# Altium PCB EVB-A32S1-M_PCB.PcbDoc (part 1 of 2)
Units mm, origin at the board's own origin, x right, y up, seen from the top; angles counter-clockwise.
Board outline 134 x 65 mm, 4 copper layers (L1 (Signal), L2 (GND), L3 (PWR), L4 (Signal)), stack 1.553 mm thick; 111 components, 86 nets, 414 pads, 386 vias.
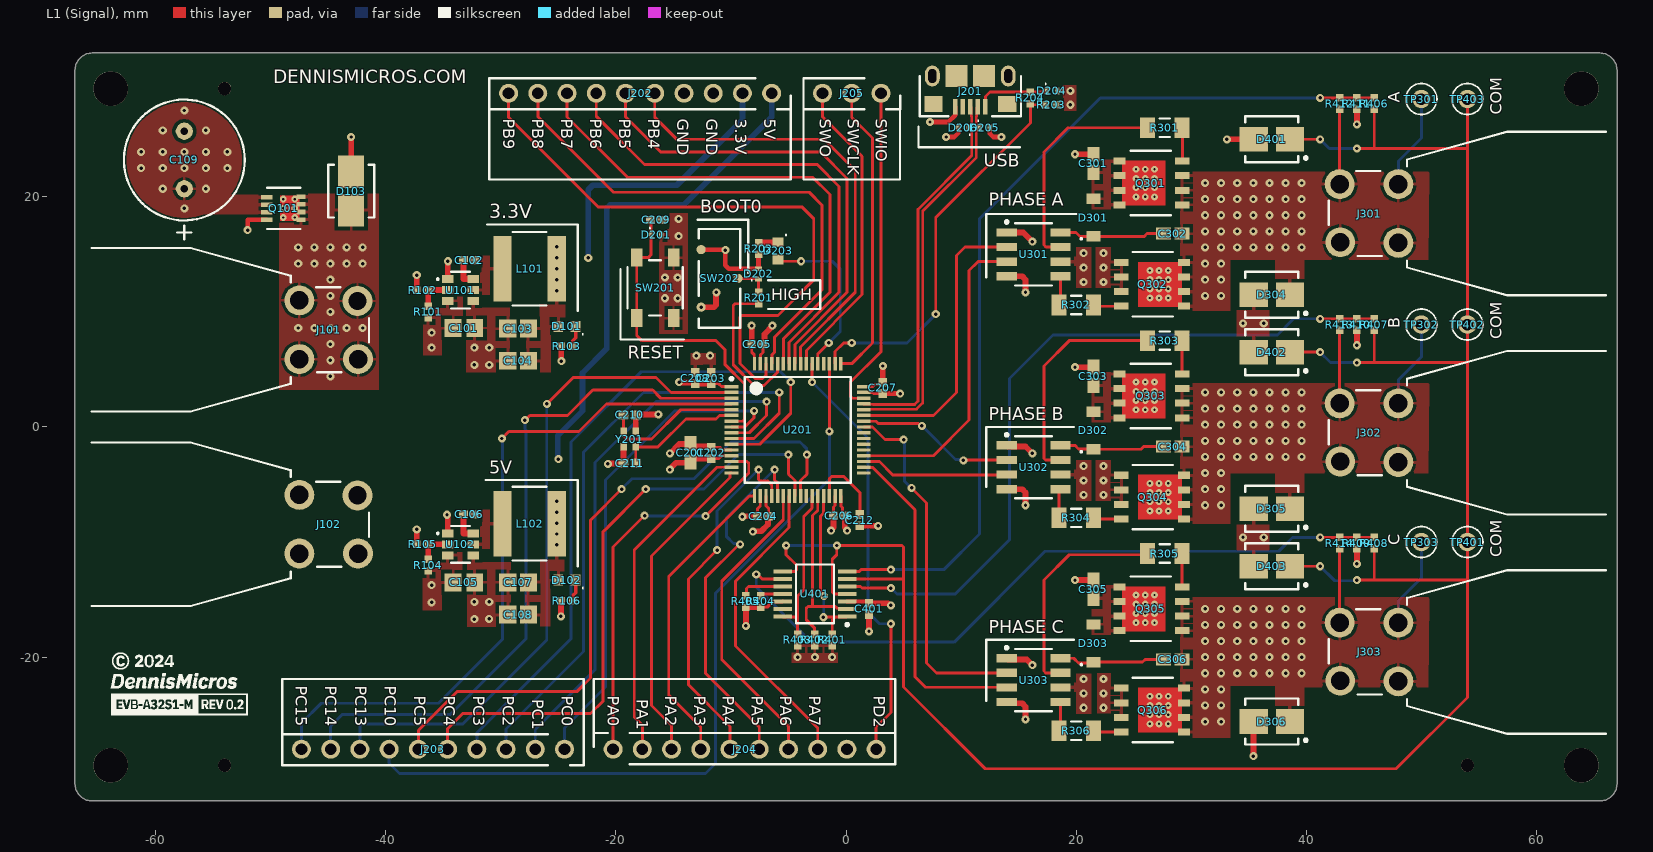
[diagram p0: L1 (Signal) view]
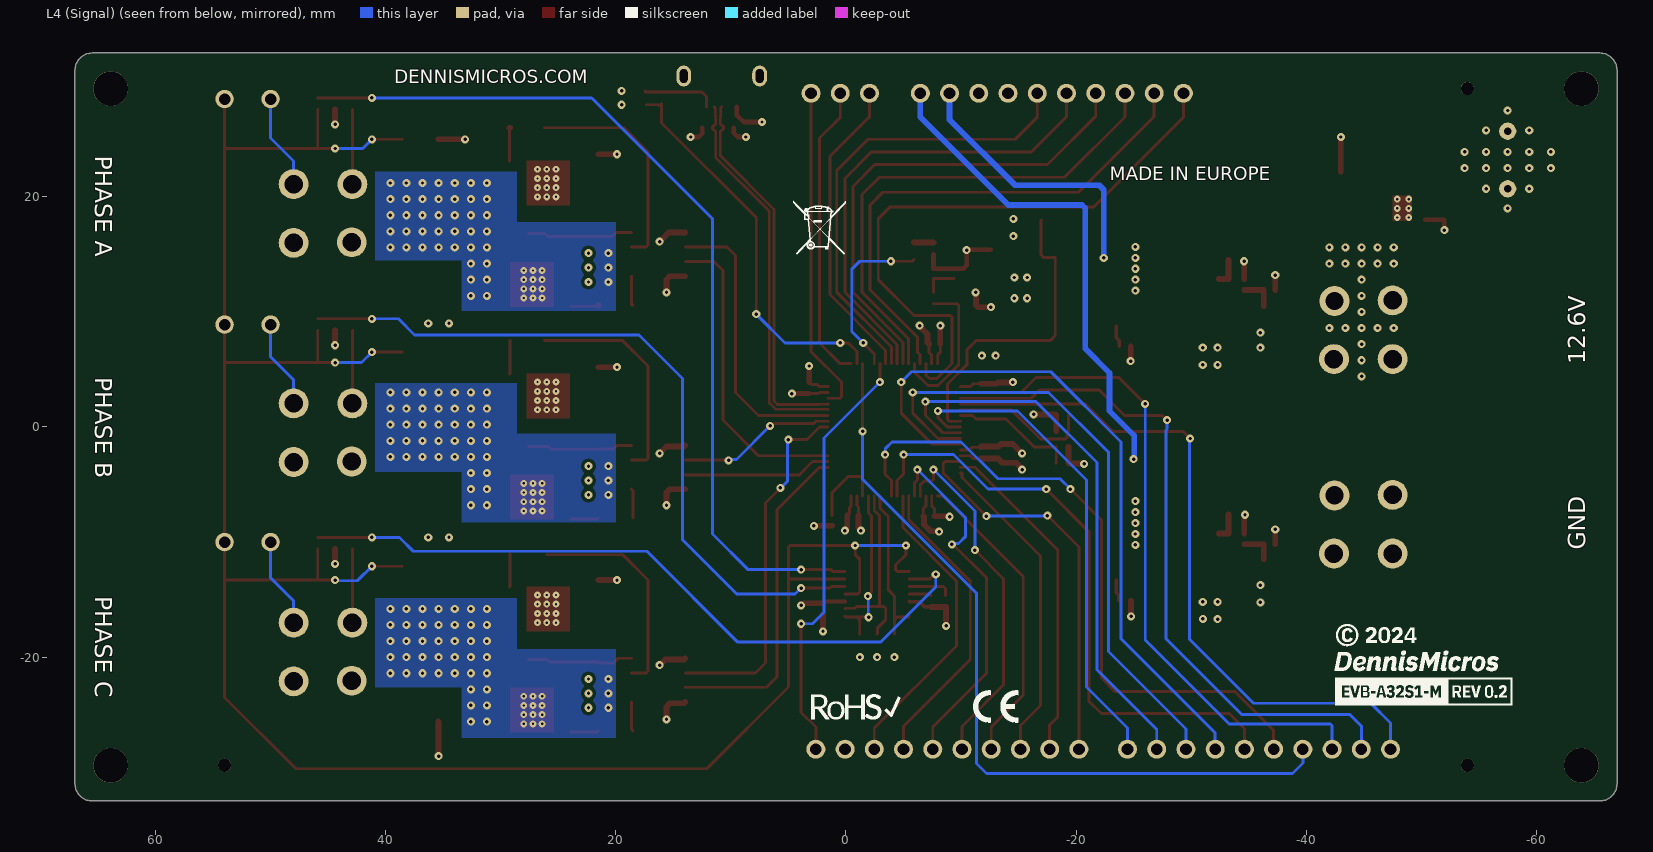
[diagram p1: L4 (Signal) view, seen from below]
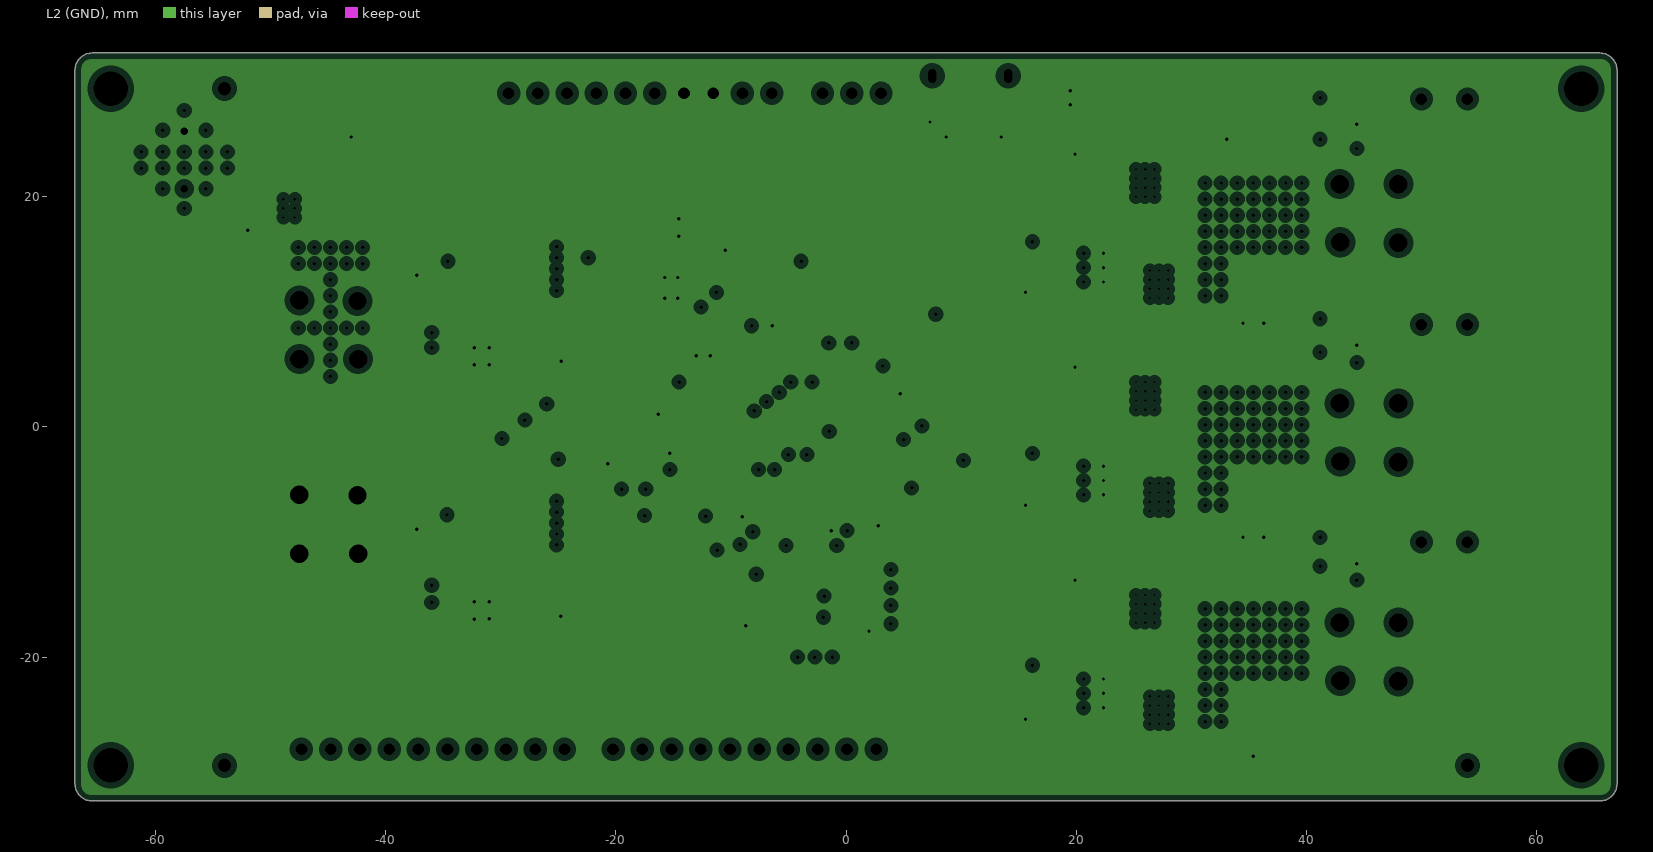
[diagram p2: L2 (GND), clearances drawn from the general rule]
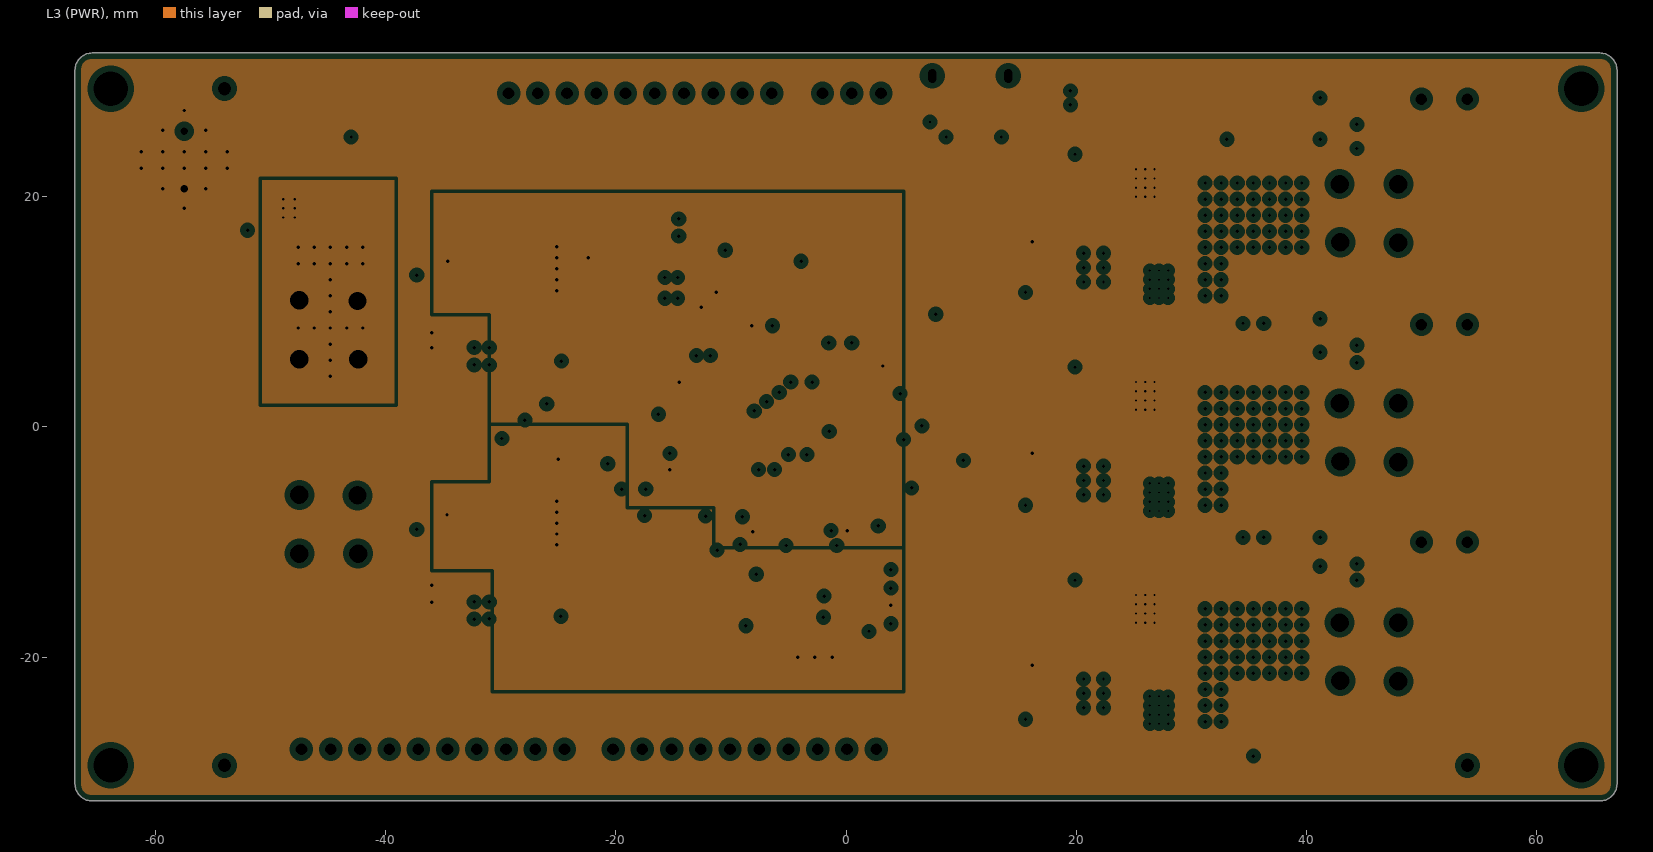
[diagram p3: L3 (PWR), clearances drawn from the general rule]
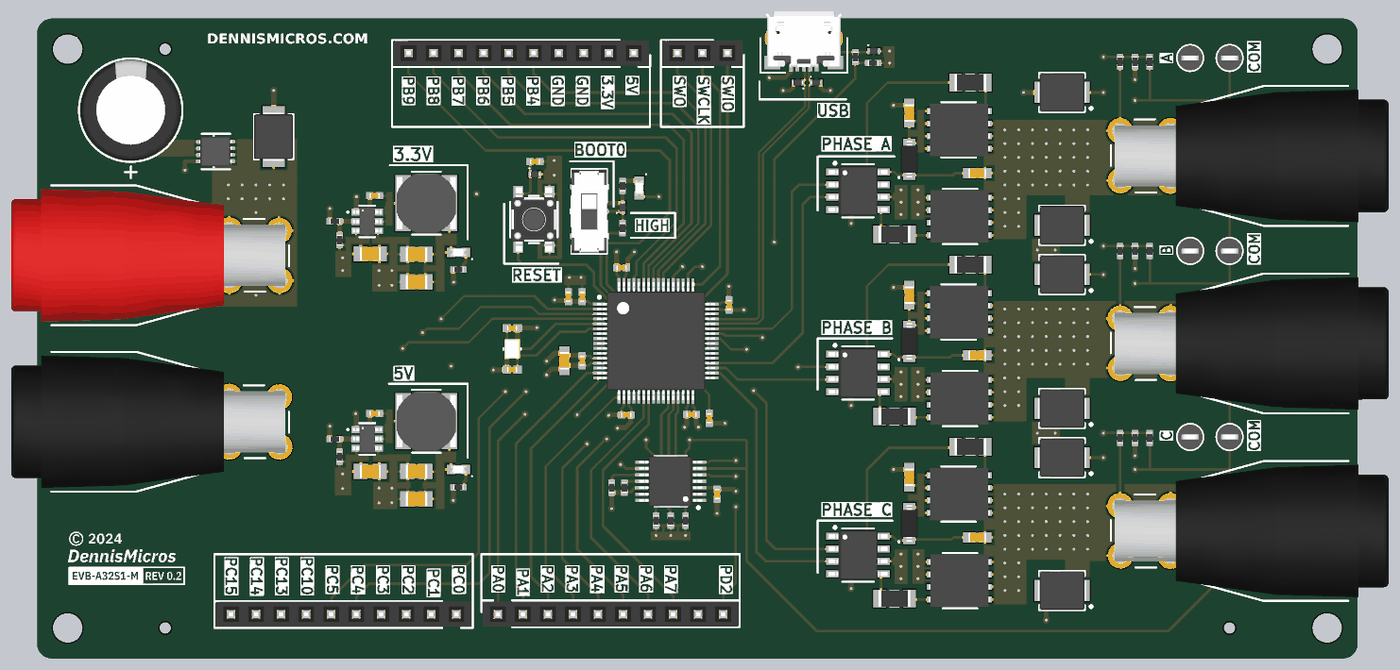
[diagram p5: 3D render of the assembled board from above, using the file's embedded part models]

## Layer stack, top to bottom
Top Solder: solder mask 0.025, SM-Peters-AS-2467-SM-DG, Dk 3.7
L1 (Signal): signal copper 0.04
PP1_1080: prepreg 0.0681, Panasonic 1080 / R-1551 (W), Dk 4.3
PP2_1080: prepreg 0.0681, Panasonic 1080 / R-1551 (W), Dk 4.3
L2 (GND): plane copper 0.035, net GND
C_FR4: core 1.13, Panasonic FR4 / R-1566(W), Dk 4.6
L3 (PWR): plane copper 0.035, net (Multiple Nets)
PP3_1080: prepreg 0.0681, Panasonic 1080 / R-1551 (W), Dk 4.3
PP4_1080: prepreg 0.0681, Panasonic 1080 / R-1551 (W), Dk 4.3
L4 (Signal): signal copper 0.04
Bottom Solder: solder mask 0.025, SM-Peters-AS-2467-SM-DG, Dk 3.7

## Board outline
-67,-31 -67,31 cw(c-65.5,31) -65.5,32.5 65.5,32.5 cw(c65.5,31) 67,31 67,-31 cw(c65.5,-31) 65.5,-32.5 -65.5,-32.5 cw(c-65.5,-31)

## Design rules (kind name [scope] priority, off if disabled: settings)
BoardOutlineClearance CopperBoardOutlineClearance [IsText = 'False'] p1: gap=0.305 ignorepadtopadclearanceinfootprint=FALSE
BoardOutlineClearance SilkscreenBoardOutlineClearance [IsText = 'True'] p2: gap=0.4 ignorepadtopadclearanceinfootprint=FALSE
Clearance [All] p1: gap=0.3 ignorepadtopadclearanceinfootprint=FALSE except(0.125: Arc-Arc Arc-Track Arc-SMDPad Arc-Text Track-Track Track-SMDPad Track-Text SMDPad-SMDPad SMDPad-Fill SMDPad-Poly SMDPad-Region SMDPad-Text THPad-Text Via-Text Fill-Fill Fill-Poly Fill-Region Fill-Text Poly-Poly Poly-Region Poly-Text Region-Region Region-Text Text-Text Text-Hole)
DiffPairsRouting DiffUSBRouting [InDifferentialPairClass('DIFF_USB')] p1: maxlimit=0.165 minlimit=0.165 mostfreqgap=0.165 toplayer_minwidth=0.23 toplayer_maxwidth=0.23 toplayer_prefwidth=0.23 bottomlayer_minwidth=0.23 bottomlayer_maxwidth=0.23 bottomlayer_prefwidth=0.23 impedanceprofiledriven=TRUE impedanceprofileid={3CFC2630-1907-411B-A5D9-8473F3C0A9A4} impedanceprofilevalue=90.000000 maxuncoupledlength=12.7
HoleSize NPTHSlotSize [HoleType = 'Slot' && PadIsPlated = 'False'] p1: absolutevalues=TRUE maxlimit=5.6 minlimit=1.8 maxpercent=80.000 minpercent=20.000
HoleSize PTHSlotSize [HoleType = 'Slot' && PadIsPlated = 'True'] p2: absolutevalues=TRUE maxlimit=2.6 minlimit=0.7 maxpercent=80.000 minpercent=20.000
HoleSize PTHSize [PadIsPlated = 'True'] p3: absolutevalues=TRUE maxlimit=5.6 minlimit=0.5 maxpercent=80.000 minpercent=20.000
HoleSize NPTHSize [PadIsPlated = 'False'] p4: absolutevalues=TRUE maxlimit=5.6 minlimit=0.5 maxpercent=80.000 minpercent=20.000
HoleToHoleClearance [All] p1: gap=0.3 allowstackedmicrovias=TRUE
MinimumAnnularRing PTHSlotMinimumAnnularRing [HoleType = 'Slot' && PadIsPlated = 'True'] p1: minimumring=0.3
MinimumAnnularRing PTHMinimumAnnularRing [PadIsPlated = 'True'] p2: minimumring=0.3
MinimumAnnularRing ViaMinimumAnnularRing [IsVia] p3: minimumring=0.1
MinimumSolderMaskSliver [All] p1: minsoldermaskwidth=0.075
PlaneClearance [All] p1: clearance=0.508
PlaneConnect [All] p1: pad.planeconnectstyle=Relief pad.reliefexpansion=0.508 pad.reliefentries=4 pad.reliefconductorwidth=0.254 pad.reliefairgap=0.3 via.planeconnectstyle=Direct via.reliefexpansion=0.508 via.reliefentries=4 via.reliefconductorwidth=0.254 via.reliefairgap=0.254
PolygonConnect [All] p1: thpad.connectstyle=Relief thpad.reliefconductorwidth=0.254 thpad.reliefentries=4 thpad.polygonreliefangle="90 Angle" thpad.airgapwidth=0.3 smdpad.connectstyle=Relief smdpad.reliefconductorwidth=0.254 smdpad.reliefentries=4 smdpad.polygonreliefangle="90 Angle" smdpad.airgapwidth=0.3 via.connectstyle=Direct via.reliefconductorwidth=0.254 via.reliefentries=4 via.polygonreliefangle="90 Angle" via.airgapwidth=0.254
RoutingVias [All] p1: holewidth=0.3 width=0.7 viastyle="Through Hole" minholewidth=0.25 minwidth=0.5 maxholewidth=0.45 maxwidth=0.7
SilkToSilkClearance [All] p1: silktosilkclearance=0.3
SilkToSolderMaskClearance [IsPad] p1: minsilkscreentomaskgap=0.15 clearancetoexposedcopper=TRUE
SolderMaskExpansion [All] p1: expansion=0.127 istentingtop=FALSE
SupplyNets "Schematic Supply Nets_2" [InNet('+VBAT')] p1: voltage=0.000
SupplyNets "Schematic Supply Nets_4" [InNet('GND')] p2: voltage=0.000
SupplyNets "Schematic Supply Nets_3" [InNet('+VCC')] p3: voltage=0.000
SupplyNets "Schematic Supply Nets_1" [InNet('+5V')] p4: voltage=0.000
SupplyNets "Schematic Supply Nets" [InNet('+3V3')] p5: voltage=0.000
UnRoutedNet [All] p1: checkbadconnections=TRUE
Width [All] p1: maxlimit=1 minlimit=0.15 preferedwidth=0.25
21 further rules are at their usual default settings.

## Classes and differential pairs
differential pair class DIFF_USB: USB_D
component class 4_EVB-A32S1-M_Sensing: C401 D401 D402 D403 R401 R402 R403 R404 R405 R406 R407 R408 R409 R410 R411 R412 R413 R414 TP401 TP402 TP403 U401
component class 3_EVB-A32S1-M_Motor: C301 C302 C303 C304 C305 C306 D301 D302 D303 D304 D305 D306 J301 J302 J303 Q301 Q302 Q303 Q304 Q305 Q306 R301 R302 R303 R304 R305 R306 TP301 TP302 TP303 U301 U302 U303
component class 2_EVB-A32S1-M_MCU: C201 C202 C203 C204 C205 C206 C207 C208 C209 C210 C211 C212 D201 D202 D203 D204 D205 D206 J201 J202 J203 J204 J205 R201 R202 R203 R204 SW201 SW202 U201 Y201
component class 1_EVB-A32S1-M_Power: C101 C102 C103 C104 C105 C106 C107 C108 C109 D101 D102 D103 J101 J102 L101 L102 Q101 R101 R102 R103 R104 R105 R106 U101 U102
differential pair USB_D: +USB_D_P -USB_D_N

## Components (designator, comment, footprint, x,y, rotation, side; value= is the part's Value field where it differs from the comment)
C101 "CL21A106KOQNNNE" C_Samsung_CL_0805_A -33.2,8.6 r180 top value=10uF
C102 "CL05B104KP5NNNC" C_Samsung_CL_0402_A -32.75,14.5 r180 top value=100nF
C103 "CC0805MKX5R6BB226" C_Yageo_CC_0805_A -28.5,8.55 r0 top value=22uF
C104 "CC0805MKX5R6BB226" C_Yageo_CC_0805_A -28.5,5.75 r0 top value=22uF
C105 "CL21A106KOQNNNE" C_Samsung_CL_0805_A -33.2,-13.5 r180 top value=10uF
C106 "CL05B104KP5NNNC" C_Samsung_CL_0402_A -32.75,-7.6 r180 top value=100nF
C107 "CC0805MKX5R6BB226" C_Yageo_CC_0805_A -28.5,-13.5 r0 top value=22uF
C108 "CC0805MKX5R6BB226" C_Yageo_CC_0805_A -28.5,-16.3 r0 top value=22uF
C109 "35ZLH470MEFC10X16" C_Rubycon_10x16mm_TH -57.5,23.2 r90 top value=470uF
C201 "CC0603KRX7R7BB105" C_Yageo_CC_0603_A -13.5,-2.25 r270 top value=1uF
C202 "CL05B104KP5NNNC" C_Samsung_CL_0402_A -11.7,-2.25 r270 top value=100nF
C203 "CL05B104KP5NNNC" C_Samsung_CL_0402_A -11.7,4.25 r270 top value=100nF
C204 "CL05B104KP5NNNC" C_Samsung_CL_0402_A -7.2,-7.75 r0 top value=100nF
C205 "CL05B104KP5NNNC" C_Samsung_CL_0402_A -7.7,7.2 r180 top value=100nF
C206 "CL05B104KP5NNNC" C_Samsung_CL_0402_A -0.6,-7.7 r0 top value=100nF
C207 "CL05B104KP5NNNC" C_Samsung_CL_0402_A 3.2,3.4 r90 top value=100nF
C208 "CL05A475MP5NRNC" C_Samsung_CL_0402_A -13.1,4.25 r270 top value=4.7uF
C209 "CL05B104KP5NNNC" C_Samsung_CL_0402_A -16.488,17.988 r180 top value=100nF
C210 "CC0402JRNPO9BN150" C_Yageo_CC_0402_A -18.8,1.05 r180 top value=15pF
C211 "CC0402JRNPO9BN150" C_Yageo_CC_0402_A -18.8,-3.15 r0 top value=15pF
C212 "CL05A475MP5NRNC" C_Samsung_CL_0402_A 1.2,-8.1 r90 top value=4.7uF
C301 "CC0603KRX7R7BB105" C_Yageo_CC_0603_A 21.5,22.9 r270 top value=1uF
C302 "CC0603KRX7R7BB105" C_Yageo_CC_0603_A 28.4,16.8 r180 top value=1uF
C303 "CC0603KRX7R7BB105" C_Yageo_CC_0603_A 21.5,4.4 r270 top value=1uF
C304 "CC0603KRX7R7BB105" C_Yageo_CC_0603_A 28.4,-1.7 r180 top value=1uF
C305 "CC0603KRX7R7BB105" C_Yageo_CC_0603_A 21.5,-14.1 r270 top value=1uF
C306 "CC0603KRX7R7BB105" C_Yageo_CC_0603_A 28.4,-20.2 r180 top value=1uF
C401 "CL05B104KP5NNNC" C_Samsung_CL_0402_A 2,-15.8 r90 top value=100nF
D101 "LTST-C190GKT" D_LED_Lite-On_Green_0603_A -24.25,8.75 r180 top
D102 "LTST-C190GKT" D_LED_Lite-On_Green_0603_A -24.25,-13.3 r180 top
D103 "SMBJ15CA-13-F" D_TVS_BI_Diodes_SMBJ15CA-13-F_A -43,20.5 r90 top value=280pF
D201 "D5V0F1U2S9-7" D_TVS_Uni_Diodes_SOD-923_B -16.488,16.688 r0 top value=5E-13F
D202 "D5V0F1U2S9-7" D_TVS_Uni_Diodes_SOD-923_B -7.588,13.312 r90 top value=5E-13F
D203 "LTST-C190GKT" D_LED_Lite-On_Green_0603_A -5.9,15.3 r270 top
D204 "D5V0F1U2S9-7" D_TVS_Uni_Diodes_SOD-923_B 17.9,29.2 r0 top value=5E-13F
D205 "D5V0F1U2S9-7" D_TVS_Uni_Diodes_SOD-923_B 12.05,26 r0 top value=5E-13F
D206 "D5V0F1U2S9-7" D_TVS_Uni_Diodes_SOD-923_B 10.2,26 r180 top value=5E-13F
D301 "B5819W-TP" D_Schottky_MCC_SOD-123 21.5,18.2 r90 top
D302 "B5819W-TP" D_Schottky_MCC_SOD-123 21.5,-0.3 r90 top
D303 "B5819W-TP" D_Schottky_MCC_SOD-123 21.5,-18.8 r90 top
D304 "SMBJ15A-13-F" D_TVS_Uni_Diodes_DO-214AA_B 37,11.5 r180 top value=800pF
D305 "SMBJ15A-13-F" D_TVS_Uni_Diodes_DO-214AA_B 37,-7.1 r180 top value=800pF
D306 "SMBJ15A-13-F" D_TVS_Uni_Diodes_DO-214AA_B 37,-25.6 r180 top value=800pF
D401 "SMBJ15A-13-F" D_TVS_Uni_Diodes_DO-214AA_B 37,25 r180 top value=800pF
D402 "SMBJ15A-13-F" D_TVS_Uni_Diodes_DO-214AA_B 37,6.5 r180 top value=800pF
D403 "SMBJ15A-13-F" D_TVS_Uni_Diodes_DO-214AA_B 37,-12.1 r180 top value=800pF
J101 "CT3151SP-2" J_CalTest_CT3151SP-2 -44.95,8.45 r0 top
J102 "CT3151SP-0" J_CalTest_CT3151SP-0 -44.95,-8.45 r0 top
J201 "10118193-0001LF" J_USB_Micro-B_Amphenol_10118193-0001LF 10.8,30.5 r180 top
J202 "PPPC101LFBN-RC" J_Sullins_01x07_Socket_2.54mm -17.89,29 r180 top
J203 "PPPC101LFBN-RC" J_Sullins_01x07_Socket_2.54mm -35.89,-28 r180 top
J204 "PPPC101LFBN-RC" J_Sullins_01x07_Socket_2.54mm -8.81,-28 r0 top
J205 "PPPC031LFBN-RC" J_Sullins_01x03_Socket_2.54mm 0.5,29 r180 top
J301 "CT3151SP-0" J_CalTest_CT3151SP-0 45.45,18.55 r180 top
J302 "CT3151SP-0" J_CalTest_CT3151SP-0 45.45,-0.5 r180 top
J303 "CT3151SP-0" J_CalTest_CT3151SP-0 45.45,-19.55 r180 top
L101 "1255AY-3R9N=P3" L_Murata_1255AY-XXXX=P3 -27.5,13.75 r0 top value=3.9uH
L102 "1255AY-4R7M=P3" L_Murata_1255AY-XXXX=P3 -27.5,-8.4 r0 top value=4.7uH
Q101 "SI7617DN-T1-GE3" Q_Vishay_PowerPACK-1212-8 -48.9,19 r0 top
Q301 "SIR182DP-T1-RE3" Q_Vishay_PowerPACK-SO-8-Single 26.75,21.2 r180 top
Q302 "SIR182DP-T1-RE3" Q_Vishay_PowerPACK-SO-8-Single 26.4,12.4 r0 top
Q303 "SIR182DP-T1-RE3" Q_Vishay_PowerPACK-SO-8-Single 26.75,2.7 r180 top
Q304 "SIR182DP-T1-RE3" Q_Vishay_PowerPACK-SO-8-Single 26.4,-6.1 r0 top
Q305 "SIR182DP-T1-RE3" Q_Vishay_PowerPACK-SO-8-Single 26.75,-15.8 r180 top
Q306 "SIR182DP-T1-RE3" Q_Vishay_PowerPACK-SO-8-Single 26.4,-24.6 r0 top
R101 "RC0402FR-07110KL" R_Yageo_RCL_0402_A -36.3,10 r270 top value=110kR
R102 "RC0402FR-0713KL" R_Yageo_RCL_0402_A -36.8,11.9 r0 top value=13kR
R103 "RC0402FR-071KL" R_Yageo_RCL_0402_A -24.25,7 r0 top value=1kR
R104 "RC0402FR-07110KL" R_Yageo_RCL_0402_A -36.3,-12 r270 top value=110kR
R105 "RC0402FR-0713KL" R_Yageo_RCL_0402_A -36.8,-10.2 r0 top value=13kR
R106 "RC0402FR-071KL" R_Yageo_RCL_0402_A -24.25,-15.1 r0 top value=1kR
R201 "RC0402FR-0710KL" R_Yageo_RCL_0402_A -7.588,11.212 r270 top value=10kR
R202 "RC0402FR-071KL" R_Yageo_RCL_0402_A -7.6,15.5 r90 top value=1kR
R203 "RC0402FR-0733KL" R_Yageo_RCL_0402_A 17.825,28 r180 top value=33kR
R204 "RC0402FR-0713KL" R_Yageo_RCL_0402_A 16.025,28.6 r90 top value=13kR
R301 "RC1206FR-07100RL" R_Yageo_RCL_1206_A 27.7,26 r0 top value=100R
R302 "RC1206FR-07100RL" R_Yageo_RCL_1206_A 20,10.6 r0 top value=100R
R303 "RC1206FR-07100RL" R_Yageo_RCL_1206_A 27.7,7.5 r0 top value=100R
R304 "RC1206FR-07100RL" R_Yageo_RCL_1206_A 20,-7.9 r0 top value=100R
R305 "RC1206FR-07100RL" R_Yageo_RCL_1206_A 27.7,-11 r0 top value=100R
R306 "RC1206FR-07100RL" R_Yageo_RCL_1206_A 20,-26.4 r0 top value=100R
R401 "RC0402FR-0710KL" R_Yageo_RCL_0402_A -1.2,-18.5 r270 top value=10kR
R402 "RC0402FR-0710KL" R_Yageo_RCL_0402_A -2.7,-18.5 r270 top value=10kR
R403 "RC0402FR-0710KL" R_Yageo_RCL_0402_A -4.2,-18.5 r270 top value=10kR
R404 "RC0402FR-0710KL" R_Yageo_RCL_0402_A -7.4,-15.15 r90 top value=10kR
R405 "RC0402FR-0710KL" R_Yageo_RCL_0402_A -8.7,-15.15 r90 top value=10kR
R406 "RC0402FR-0733KL" R_Yageo_RCL_0402_A 45.9,28.1 r90 top value=33kR
R407 "RC0402FR-0733KL" R_Yageo_RCL_0402_A 45.9,8.9 r90 top value=33kR
R408 "RC0402FR-0733KL" R_Yageo_RCL_0402_A 45.9,-10.1 r90 top value=33kR
R409 "RC0402FR-0710KL" R_Yageo_RCL_0402_A 44.4,-10.1 r90 top value=10kR
R410 "RC0402FR-0710KL" R_Yageo_RCL_0402_A 44.4,8.9 r90 top value=10kR
R411 "RC0402FR-0710KL" R_Yageo_RCL_0402_A 44.4,28.1 r90 top value=10kR
R412 "RC0402FR-0733KL" R_Yageo_RCL_0402_A 42.9,28.1 r270 top value=33kR
R413 "RC0402FR-0733KL" R_Yageo_RCL_0402_A 42.9,8.9 r270 top value=33kR
R414 "RC0402FR-0733KL" R_Yageo_RCL_0402_A 42.9,-10.1 r270 top value=33kR
SW201 "PTS647SN50SMTR2LFS" SW_Tactitle_SPST_C&K_PTS647SN50SMTR2LFS -16.588,12.088 r90 top
SW202 "JS102011JCQN" SW_Slide_C&K_JS102011JCQN -10.988,12.912 r270 top
TP301 "5001" TP_Keystone_TH 50,28.5 r90 top
TP302 "5001" TP_Keystone_TH 50,8.9 r90 top
TP303 "5001" TP_Keystone_TH 50,-10 r90 top
TP401 "5001" TP_Keystone_TH 54,-10 r90 top
TP402 "5001" TP_Keystone_TH 54,8.9 r90 top
TP403 "5001" TP_Keystone_TH 54,28.5 r90 top
U101 "AP63203WU-7" U_Diodes_AP623xx -33.5,11.9 r270 top
U102 "AP63205WU-7" U_Diodes_AP623xx -33.5,-10.2 r270 top
U201 "STM32F401RET6" U_ST_STM32F401xD/xE_B -4.2,-0.25 r0 top
U301 "IR2103STRPBF" U_Infineon_8-SOIC_3.9mm 16.3,15 r0 top
U302 "IR2103STRPBF" U_Infineon_8-SOIC_3.9mm 16.3,-3.5 r0 top
U303 "IR2103STRPBF" U_Infineon_8-SOIC_3.9mm 16.3,-22 r0 top
U401 "LM339APWR" U_TI_14-TSSOP-5.00x4.40mm_0.62mm_B -2.7,-14.5 r180 top
Y201 "ECS-240-12-37B-CKY-TR" Y_Crystal_GND24_ECS_240-12-37B-CKY-TR -18.8,-1.05 r270 top

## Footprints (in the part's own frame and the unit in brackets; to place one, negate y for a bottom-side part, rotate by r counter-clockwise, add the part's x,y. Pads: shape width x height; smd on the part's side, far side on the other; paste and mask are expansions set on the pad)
C_Rubycon_10x16mm_TH [mm]
  round 1.5 hole 0.65: 1(-2.5,0) 2(2.5,0)
  silkscreen extent -6.9,-5.25 5.25,5.25, body extent -5.11,-5.1 5.11,5.1, height 16.46
C_Samsung_CL_0402_A [mm] "Chip Capacitor, 2-Leads, Body 1.00x0.50mm, IPC Low Density"
  rect 0.76x0.72 smd mask+0.05: 1(-0.49,0) 2(0.49,0)
  body extent -0.53,-0.28 0.53,0.28, height 0.55
C_Samsung_CL_0805_A [mm] "Chip Capacitor, 2-Leads, Body 2.00x1.25mm, IPC Low Density"
  rect 1.45x1.55 smd: 1(-0.95,0) 2(0.95,0)
  body extent -1.07,-0.7 1.07,0.7, height 1.4
C_Yageo_CC_0402_A [mm] "Yageo series CC Chip Capacitor, 2-Leads, Body 1.00x0.50mm, IPC Low Density"
  rect 0.86x0.8 smd mask+0.07: 1(-0.55,0) 2(0.55,0)
  body extent -0.53,-0.28 0.53,0.28, height 0.7
C_Yageo_CC_0603_A [mm] "Yageo series CC Chip Capacitor, 2-Leads, Body 1.60x0.80mm, IPC Low Density"
  rect 1.3x1.05 smd mask+0.09: 1(-0.8,0) 2(0.8,0)
  body extent -0.9,-0.5 0.9,0.5, height 1
C_Yageo_CC_0805_A [mm] "Yageo series CC Chip Capacitor, 2-Leads, Body 2.00x1.25mm, IPC Low Density"
  rect 1.5x1.55 smd mask+0.09: 1(-0.9,0) 2(0.9,0)
  body extent -1.1,-0.72 1.1,0.72, height 1.45
D_LED_Lite-On_Green_0603_A [mm] "Chip Diode, 2-Leads, Body 1.60x0.70mm, IPC Low Density"
  rect 0.85x0.95 smd: 1(-0.75,0) 2(0.75,0)
  silkscreen extent -1.44,0.64 -1.34,0.74, body extent -0.8,-0.4 0.8,0.4, height 0.8
D_Schottky_MCC_SOD-123 [mm]
  rect 0.91x1.22 smd: 1(-1.635,0) 2(1.635,0)
  silkscreen extent -1.89,1.01 -1.81,1.09, body extent -1.83,-0.85 1.88,0.85, height 1.21
D_TVS_BI_Diodes_SMBJ15CA-13-F_A [mm] "Molded Diode, 2-Leads, Body 4.31x3.62mm, IPC Low Density"
  rect 2.85x2.25 smd: 1(-1.675,0) 2(1.675,0)
  silkscreen extent -2.3,-2 2.3,2, body extent -2.5,-1.97 2.5,1.97, height 2.44
D_TVS_Uni_Diodes_DO-214AA_B [mm] "Molded Diode, 2-Leads, Body 4.31x3.62mm, IPC Medium Density"
  rect 2.45x2.15 smd: 1(-1.575,0) 2(1.575,0)
  silkscreen extent -3.08,-2 2.3,2, body extent -2.5,-1.97 2.5,1.97, height 2.5
D_TVS_Uni_Diodes_SOD-923_B [mm] "SODFL, 2-Leads, Body 0.60x1.00mm, IPC Medium Density"
  rect 0.4x0.6 smd: 1(-0.45,0) 2(0.45,0)
  silkscreen extent -0.6,0.55 -0.5,0.65, body extent -0.5,-0.33 0.5,0.33, height 0.4
J_CalTest_CT3151SP-0 [mm] "CalTest Banana Jack Connector Standard Banana Solder Black"
  round 2.6 hole 1.6: 1(-2.55,2.55) 2(2.5,2.5) 3(-2.55,-2.55) 4(2.55,-2.55)
  silkscreen extent -20.6,-7.1 3.5,7.1, body extent -24.69,-6.73 3.11,6.73, height 14.35
J_CalTest_CT3151SP-2 [mm] "CalTest Banana Jack Connector Standard Banana Solder Red"
  round 2.6 hole 1.6: 1(-2.55,2.55) 2(2.5,2.5) 3(-2.55,-2.55) 4(2.55,-2.55)
  silkscreen extent -20.6,-7.1 3.5,7.1, body extent -24.69,-6.73 3.11,6.73, height 14.35
J_Sullins_01x03_Socket_2.54mm [mm]
  round 1.65 hole 1.02 mask+0.05: 1(-2.54,0) 2(0,0) 3(2.54,0)
  silkscreen extent -4.21,-1.3 4.19,1.4, body extent -4.06,-1.27 4.06,1.27, height 8.5
J_Sullins_01x07_Socket_2.54mm [mm]
  round 1.65 hole 1.02 mask+0.05: 1(-11.43,0) 2(-8.89,0) 3(-6.35,0) 4(-3.81,0) 5(-1.27,0) 6(1.27,0) 7(3.81,0) 8(6.35,0) 9(8.89,0) 10(11.43,0)
  silkscreen extent -13.1,-1.3 13.1,1.4, body extent -12.95,-1.27 12.95,1.27, height 8.5
J_USB_Micro-B_Amphenol_10118193-0001LF [mm] "USB - micro B USB 2.0 Receptacle Connector 5 Position Surface Mount, Right Angle; Through Hole"
  rect 0.4x1.35 smd mask+0.05: 1(-1.3,2.675) 2(-0.65,2.675) 3(0,2.675) 4(0.65,2.675) 5(1.3,2.675)
  rect 1.6x1.4 smd mask+0.05: 6(-3.2,2.45) 7(3.2,2.45)
  rect 1.9x1.9 smd mask+0.05: 8(1.2,0) 9(-1.2,0)
  oval 1.3x1.8 hole 0.7 slot 1.2 at 90 deg mask+0.05: 10(3.3,0) 11(-3.3,0)
  silkscreen extent -4.4,0 4.4,3.5, body extent -3.93,-2.76 3.93,2.95, height 2.81
L_Murata_1255AY-XXXX=P3 [mm]
  rect 1.6x5.7 smd: 1(-2.35,0) 2(2.35,0)
  silkscreen extent -1.45,-3.2 1.45,3.2, body extent -3,-3 3,3, height 4.51
Q_Vishay_PowerPACK-1212-8 [mm]
  rect 0.99x0.405 smd mask+0.05: 1(-1.435,0.975) 2(-1.435,0.315) 3(-1.435,-0.345) 4(-1.435,-1.005)
  rect 0.76x0.405 smd mask+0.05: 5(1.55,-0.98) 6(1.55,-0.32) 7(1.55,0.34) 8(1.55,1)
  L1 (Signal) region: -0.306,-1.117 1.419,-1.117 1.419,1.117 -0.306,1.117
  silkscreen extent -1.4,-1.8 1.5,1.8, body extent -1.65,-1.65 1.65,1.65, height 1.13
Q_Vishay_PowerPACK-SO-8-Single [mm]
  rect 1.27x0.61 smd: 1(-2.485,1.905) 2(-2.485,0.635) 3(-2.485,-0.635) 4(-2.485,-1.905)
  rect 1.02x0.61 smd: 5(2.98,-1.905) 6(2.98,-0.635) 7(2.98,0.635) 8(2.98,1.905)
  L1 (Signal) region: -1.033,-1.955 2.777,-1.955 2.777,1.955 -1.033,1.955
  silkscreen extent -1.5,-2.8 2,2.8, body extent -2.92,-2.65 3.32,2.65, height 1.09
R_Yageo_RCL_0402_A [mm] "Yageo series RC_L Chip Resistor, 2-Leads, Body 1.00x0.50mm, IPC Low Density"
  rect 0.65x0.65 smd mask+0.05: 1(-0.5,0) 2(0.5,0)
  body extent -0.53,-0.28 0.53,0.28, height 0.4
R_Yageo_RCL_1206_A [mm] "Yageo series RC_L Chip Resistor, 2-Leads, Body 3.10x1.60mm, IPC Low Density"
  rect 1.3x1.8 smd: 1(-1.5,0) 2(1.5,0)
  silkscreen extent -0.45,-0.8 0.45,0.8, body extent -1.6,-0.85 1.6,0.85, height 0.65
SW_Slide_C&K_JS102011JCQN [mm] "Slide Switch SPDT Surface Mount"
  round 0.8 smd mask+0.05: 1(-2.5,-1.6) 2(0,1.6) 3(2.5,-1.6)
  silkscreen extent -4.3,-1.8 4.3,1.8, body extent -4.25,-2 4.25,2, height 5.4
SW_Tactitle_SPST_C&K_PTS647SN50SMTR2LFS [mm] "Tactitle switch SPST-NO 4.5mm x 4.5mm"
  rect 1.55x1 smd mask+0.05: 1(-2.625,1.6) 2(2.625,1.6) 3(-2.625,-1.6) 4(2.625,-1.6)
  silkscreen extent -2.4,-2.4 2.4,2.4, body extent -3.25,-2.25 3.25,2.25, height 5
TP_Keystone_TH [mm]
  round 1.6 hole 1: 1(0,0)
  silkscreen extent -1.35,-1.35 1.35,1.35, body extent -1.27,-1.26 1.27,1.26, height 4.57
U_Diodes_AP623xx [mm]
  rect 0.7x1 smd mask+0.05: 1(-0.95,-1.1) 2(0,-1.1) 3(0.95,-1.1) 4(0.95,1.1) 5(0,1.1) 6(-0.95,1.1)
  silkscreen extent -1.6,-2.01 1.6,0.8, body extent -1.45,-1.45 1.45,1.45, height 0.91
U_Infineon_8-SOIC_3.9mm [mm] "SOIC, 8-Leads, Body 4.90x3.90mm, Pitch 1.27mm, IPC Medium Density"
  rect 1.78x0.72 smd: 1(-2.34,1.905) 2(-2.34,0.635) 3(-2.34,-0.635) 4(-2.34,-1.905) 5(2.34,-1.905) 6(2.34,-0.635) 7(2.34,0.635) 8(2.34,1.905)
  silkscreen extent -2.46,-2.7 1.6,2.94, body extent -3,-2.5 3,2.5, height 1.75
U_ST_STM32F401xD/xE_B [mm] "TSQFP, 64-Leads, Body 10.00x10.00mm, Pitch 0.50mm, IPC Medium Density"
  rect 1.2x0.3 smd mask+0.05: 1(-5.75,3.75) 2(-5.75,3.25) 3(-5.75,2.75) 4(-5.75,2.25) 5(-5.75,1.75) 6(-5.75,1.25) 7(-5.75,0.75) 8(-5.75,0.25) 9(-5.75,-0.25) 10(-5.75,-0.75) 11(-5.75,-1.25) 12(-5.75,-1.75) 13(-5.75,-2.25) 14(-5.75,-2.75) 15(-5.75,-3.25) 16(-5.75,-3.75) 33(5.75,-3.75) 34(5.75,-3.25) 35(5.75,-2.75) 36(5.75,-2.25) 37(5.75,-1.75) 38(5.75,-1.25) 39(5.75,-0.75) 40(5.75,-0.25) 41(5.75,0.25) 42(5.75,0.75) 43(5.75,1.25) 44(5.75,1.75) 45(5.75,2.25) 46(5.75,2.75) 47(5.75,3.25) 48(5.75,3.75)
  rect 0.3x1.2 smd mask+0.05: 17(-3.75,-5.75) 18(-3.25,-5.75) 19(-2.75,-5.75) 20(-2.25,-5.75) 21(-1.75,-5.75) 22(-1.25,-5.75) 23(-0.75,-5.75) 24(-0.25,-5.75) 25(0.25,-5.75) 26(0.75,-5.75) 27(1.25,-5.75) 28(1.75,-5.75) 29(2.25,-5.75) 30(2.75,-5.75) 31(3.25,-5.75) 32(3.75,-5.75) 49(3.75,5.75) 50(3.25,5.75) 51(2.75,5.75) 52(2.25,5.75) 53(1.75,5.75) 54(1.25,5.75) 55(0.75,5.75) 56(0.25,5.75) 57(-0.25,5.75) 58(-0.75,5.75) 59(-1.25,5.75) 60(-1.75,5.75) 61(-2.25,5.75) 62(-2.75,5.75) 63(-3.25,5.75) 64(-3.75,5.75)
  silkscreen extent -5.87,-4.6 4.6,4.6, body extent -6,-6 6,6, height 1.6
U_TI_14-TSSOP-5.00x4.40mm_0.62mm_B [mm] "TSOP, 14-Leads, Body 5.00x4.40mm, Pitch 0.65mm, IPC Medium Density"
  rect 1.6x0.35 smd mask+0.05: 1(-2.8,1.95) 2(-2.8,1.3) 3(-2.8,0.65) 4(-2.8,0) 5(-2.8,-0.65) 6(-2.8,-1.3) 7(-2.8,-1.95) 8(2.8,-1.95) 9(2.8,-1.3) 10(2.8,-0.65) 11(2.8,0) 12(2.8,0.65) 13(2.8,1.3) 14(2.8,1.95)
  silkscreen extent -2.93,-2.55 1.65,2.8, body extent -3.2,-2.55 3.2,2.55, height 1.2
Y_Crystal_GND24_ECS_240-12-37B-CKY-TR [mm]
  rect 0.65x0.55 smd mask+0.05: 1(-0.675,-0.525) 2(0.675,-0.525) 3(0.675,0.525) 4(-0.675,0.525)
  silkscreen extent -0.1,-0.9 0.1,0.9, body extent -1,-0.8 1,0.8, height 0.51

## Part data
C101 C105: library part CMP-001-00022-4, "Multilayer Ceramic Capacitor, 10 uF, 16 V, ± 10%, X5R, 0805 [2012 Metric]", Case Code (Imperial)=0805, Case Code (Metric)=2012, Dielectric=X7R, Max Operating Temperature=85°C, Min Operating Temperature=-55°C, Package Quantity=1, Tolerance=10%, Voltage=16V
C102 C106 C202 C203 C204 C205 C206 C207 C209 C401: library part CMP-001-00023-3, "Multilayer Ceramic Capacitor, 0.1 uF, 10 V, ± 10%, X7R, 0402 [1005 Metric]", Case Code (Imperial)=0402, Case Code (Metric)=1005, Dielectric=X7R, Max Operating Temperature=125°C, Min Operating Temperature=-55°C, Package Quantity=1, Tolerance=10%, Voltage Rating=10V
C103 C104 C107 C108: library part CMP-001-00014-8, "Multilayer Ceramic Capacitor, 22 uF, 10 V, ± 20%, X5R, 0805 [2012 Metric]", Case Code (Imperial)=0805, Case Code (Metric)=2012, Dielectric=X5R, Max Operating Temperature=85°C, Min Operating Temperature=-55°C, Tolerance=20%, Voltage Rating=10V
C109: library part CMP-001-00025-5, "Cap Aluminum 470uF 35V 20% (10 X 16mm) Radial 5mm 1760mA 10000h 105 C Bulk", Case/Package=Radial, Dielectric Material=Aluminium, Leakage Current=3uA, Max Operating Temperature=105°C, Min Operating Temperature=-40°C, Ripple Current=1.76A, Tolerance=20%, Voltage=35V
C201 C301 C302 C303 C304 C305 C306: library part CMP-001-00019-4, "Multilayer Ceramic Capacitor, 1 uF, 16 V, ± 10%, X7R, 0603 [1608 Metric]", Case Code (Imperial)=0603, Case Code (Metric)=1608, Dielectric=X7R, Max Operating Temperature=125°C, Min Operating Temperature=-55°C, Package Quantity=1, Tolerance=10%, Voltage=16V
C208 C212: library part CMP-001-00024-3, "Multilayer Ceramic Capacitor, 4.7 uF, 10 V, ± 20%, X5R, 0402 [1005 Metric]", Case Code (Imperial)=0402, Case Code (Metric)=1005, Dielectric=X5R, Max Operating Temperature=85°C, Min Operating Temperature=-55°C, Tolerance=20%, Voltage Rating=10V
C210 C211: library part CMP-001-00017-13, "Multilayer Ceramic Capacitor, 15 pF, 10 V, ± 5%, X7R, 0402 [1005 Metric]", Case Code (Imperial)=0402, Case Code (Metric)=1005, Dielectric=C0G, Dielectric Material=Ceramic, Insulation Resistance=100GR, Max Operating Temperature=125°C, Min Operating Temperature=-55°C, Package Quantity=1, Temperature Coefficient=30ppm/°C, Tolerance=5%, Voltage=50V
D101 D102 D203: library part CMP-007-00001-3, "LED Uni-Color Green 565nm 2-Pin Chip LED T/R", Case Code (Imperial)=0603, Case Code (Metric)=1608, Color=Green, Forward Current=30mA, Forward Voltage=2.1V, Lens Color=Colorless, Max Operating Temperature=85°C, Min Operating Temperature=-55°C, Package Quantity=1, Power Dissipation=100mW, Reverse Voltage=5V, Test Current=10mA, Voltage=2V
D103: library part CMP-004-00000-11, "Tvs Diode, Bidir, 15V, 600W, Do-214Aa Rohs Compliant: Yes", Breakdown Voltage=19.2V, Case/Package=SMB, Clamping Voltage=24.4V, Leakage Current=5uA, Max Operating Temperature=150°C, Max Output current=24A, Max Power Dissipation=600W, Min Breakdown Voltage=16.7V, Min Operating Temperature=-55°C, Package Quantity=3000, Power Line Protection=No, Reverse Standoff Voltage=15V, Test Current=1mA
D201 D202 D204 D205 D206: library part CMP-004-00007-1, "Diode TVS Dual Uni-Dir 5.5V 250000W 2-Pin SOD-923 T/R", Breakdown Voltage=6V, Case/Package=SOD-923-2, Clamping Voltage=10V, Max Operating Temperature=150°C, Max Power Dissipation=250mW, Max Reverse Leakage Current=100nA, Max Surge Current=1.5A, Min Operating Temperature=-65°C, Package Quantity=10000, Peak Pulse Power=250kW, Power Line Protection=Yes, Reverse Standoff Voltage=5.5V
D301 D302 D303: library part CMP-000001-2, "Rectifier Diode, Schottky, 1 Phase, 1 Element, 1A, 40V V(RRM), Silicon", Average Rectified Current=1A, Forward Voltage=550mV, Max Forward Surge Current (Ifsm)=10A, Max Operating Temperature=125°C, Max Power Dissipation=250mW, Max Repetitive Reverse Voltage (Vrrm)=40V, Max Reverse Current=1mA, Max Reverse Voltage (DC)=20V, Min Operating Temperature=-65°C, Package Quantity=3000
D304 D305 D306 D401 D402 D403: library part CMP-004-00005-2, "TVS Diode Single Uni-Dir 15V 600W 2-Pin SMB T/R / TVS DIODE 15VWM 24.4VC SMB", Breakdown Voltage=19.2V, Case/Package=SMB, Clamping Voltage=24.4V, Forward Voltage=5V, Leakage Current=5uA, Max Operating Temperature=150°C, Max Output current=24A, Max Power Dissipation=600W, Min Breakdown Voltage=16.7V, Min Operating Temperature=-55°C, Package Quantity=3000, Power Line Protection=No, Reverse Standoff Voltage=15V, Test Current=1mA
J101: library part CMP-002-00001-14, "Conn 4mm Safety Banana Jack F 1 POS Solder RA Thru-Hole 1 Port Bag", Color=Red, Max Operating Temperature=80°C, Min Operating Temperature=-20°C
J102 J301 J302 J303: library part CMP-002-00000-17, "Conn 4mm Safety Banana Jack F 1 POS Solder RA Thru-Hole 1 Port Bag", Color=Black, Max Operating Temperature=80°C, Min Operating Temperature=-20°C
J201: library part CMP-002-00002-12, "Usb Connector, 5 Contact(S), Female, Right Angle, Surface Mount Terminal, Locking, Receptacle", Color=Black, Current Rating=1.8A, Flammability Rating="UL94 V-0", Insulation Resistance=1GR, Max Operating Temperature=85°C, Max Voltage Rating (AC)=100V, Min Operating Temperature=-55°C, Package Quantity=1200
J202 J203 J204: library part CMP-002-00003-8, "10 Position Total Single Row 2.54 mm Pitch Straight Female Header", Color=Black, Current Rating=3A, Max Operating Temperature=105°C, Min Operating Temperature=-40°C, Package Quantity=1000, Voltage Rating=250V
J205: library part CMP-002-00004-8, "3 Position Total Single Row 2.54 mm Pitch Straight Female Header", Flammability Rating="UL94 V-0", Insulation Color=Black, Max Operating Temperature=105°C, Min Operating Temperature=-40°C, Voltage Rating=250V
L101: library part CMP-006-00002-7, "Inductor Power Shielded Wirewound 3.9uH 30% 100KHz Ferrite 4.2A 0.0264Ohm DCR 2424 T/R", Case/Package=Nonstandard, Current Rating=4.2A, DC Resistance (DCR)=26.4mR, Max Operating Temperature=85°C, Min Operating Temperature=-40°C, Saturation Current=4.7A, Test Frequency=100kHz, Tolerance=30%
L102: library part CMP-006-00001-10, "Inductor Power Shielded Wirewound 4.7uH 20% 100KHz Ferrite 4A 0.0276Ohm DCR 2424 T/R", Case/Package=Nonstandard, Current Rating=4.5A, DC Resistance (DCR)=27.6mR, Inductance Tolerance=20%, Max DC Current=4A, Max Operating Temperature=85°C, Min Operating Temperature=-40°C, Test Frequency=100kHz
Q101: library part CMP-00000-19, "P CHANNEL MOSFET, -30V, 35A; Transistor; Transistor Polarity: P Channel; Continuous Drain Current Id: -35A; Source", Continuous Drain Current (ID)=-35A, Drain to Source Breakdown Voltage=-30V, Drain to Source Resistance=12.3mR, Gate to Source Voltage (Vgs)=25V, Input Capacitance=1.8nF, Max Operating Temperature=150°C, Max Power Dissipation=52W, Min Operating Temperature=-55°C, Package Quantity=3000, Power Dissipation=3.7W, Threshold Voltage=-2.5V
Q301 Q302 Q303 Q304 Q305 Q306: library part CMP-013-00000-7, "TrenchFET Gen IV Power MOSFET N-Channel Single 60V VDS ±20V VGS 60A ID 8-Pin PowerPAK SOIC T/R", Continuous Drain Current (ID)=60A, Drain to Source Voltage (Vdss)=60V, Input Capacitance=3.25nF, Max Operating Temperature=150°C, Max Power Dissipation=69.4W, Min Operating Temperature=-55°C
R101 R104: library part CMP-009-00000-11, "SMD Chip Resistor, 110 kOhm, ± 1%, 63 mW, 0402 [1005 Metric], Thick Film, General Purpose", Case Code (Imperial)=0402, Case Code (Metric)=1005, Max Operating Temperature=155°C, Max Power Dissipation=63mW, Min Operating Temperature=-55°C, Resistance Tolerance=1%, Resistor Type="Thick Film", Temperature Coefficient=100ppm/°C, Voltage Rating=50V
R102 R105 R204: library part CMP-009-00001-11, "SMD Chip Resistor, 13 kOhm, ± 1%, 63 mW, 0402 [1005 Metric], Thick Film, General Purpose", Case Code (Imperial)=0402, Case Code (Metric)=1005, Max Operating Temperature=155°C, Max Power Dissipation=63mW, Min Operating Temperature=-55°C, Package Quantity=10000, Power Rating=62.5mW, Temperature Coefficient=100ppm/°C, Tolerance=1%, Voltage Rating=50V
R103 R106 R202: library part CMP-009-00002-11, "SMD Chip Resistor, 1 kOhm, ± 1%, 62.5 mW, 0402 [1005 Metric], Thick Film, General Purpose", Case Code (Imperial)=0402, Case Code (Metric)=1005, Max Operating Temperature=155°C, Max Power Dissipation=63mW, Min Operating Temperature=-55°C, Power Rating=62.5mW, Resistance Tolerance=1%, Resistor Type="Thick Film", Temperature Coefficient=100ppm/°C, Voltage Rating=50V
R201 R401 R402 R403 R404 R405 R409 R410 R411: library part CMP-009-00003-11, "SMD Chip Resistor, 10 kOhm, ± 1%, 62.5 mW, 0402 [1005 Metric], Thick Film, General Purpose", Case Code (Imperial)=0402, Case Code (Metric)=1005, Max Operating Temperature=155°C, Max Power Dissipation=63mW, Min Operating Temperature=-55°C, Power Rating=62.5mW, Resistance Tolerance=1%, Resistor Type="Thick Film", Temperature Coefficient=100ppm/°C, Voltage Rating=50V
R203 R406 R407 R408 R412 R413 R414: library part CMP-009-00005-12, "SMD Chip Resistor, 33 kOhm, ± 1%, 63 mW, 0402 [1005 Metric], Thick Film, General Purpose", Case Code (Imperial)=0402, Case Code (Metric)=1005, Max Operating Temperature=155°C, Max Power Dissipation=63mW, Min Operating Temperature=-55°C, Package Quantity=1, Resistance Tolerance=1%, Resistor Type="Thick Film", Temperature Coefficient=100ppm/°C, Voltage Rating=50V
R301 R302 R303 R304 R305 R306: library part CMP-009-00004-12, "SMD Chip Resistor, 100 Ohm, ± 1%, 250 mW, 1206 [3216 Metric], Thick Film, General Purpose", Case Code (Imperial)=1206, Case Code (Metric)=3216, Max Operating Temperature=155°C, Max Power Dissipation=250mW, Min Operating Temperature=-55°C, Package Quantity=5000, Resistance Tolerance=1%, Resistor Type="Thick Film", Temperature Coefficient=100ppm/°C, Voltage Rating=200V
SW201: library part CMP-011-00000-13, "Switch Tactile N.O. SPST Round Button Gull Wing 0.05A 12VDC 100000Cycles 0.98N SMD T/R", Max Operating Temperature=70°C, Min Operating Temperature=-20°C, Operating Force=100gf, Ratings=IP40
SW202: library part CMP-011-00001-10, "JS Series Sub-Miniature Slide Switch SPDT On-On Top Slide 0.3A 6VDC J-Lead Surface Mount T/R", Max Operating Temperature=85°C, Min Operating Temperature=-40°C, Voltage Rating (DC)=6V
TP301 TP302 TP303 TP401 TP402 TP403: library part CMP-000000-5, "TEST POINT, PCB, THROUGH HOLE; Product R; Range: -; Connector Colour: Black; Mounting: Through Hole", Color=Black, Package Quantity=100
U101: library part CMP-019-00004-17, "AP63203 Series 3.3 V 2 A SMT Fixed Low IQ Synchronous Buck - TSOT-26", Max Operating Temperature=85°C, Max Supply Voltage=32V, Min Operating Temperature=-40°C, Min Supply Voltage=3.8V, Nominal Supply Current=22uA, Output Current=2A, Output Voltage=3.3V, Switching Frequency=1.1MHz
U102: library part CMP-019-00003-17, "AP63205 Series 32 V 2 A 1.1 MHz Synchronous Buck Converter -TSOT-26", Max Operating Temperature=85°C, Max Supply Voltage=32V, Min Operating Temperature=-40°C, Min Supply Voltage=3.8V, Nominal Supply Current=22uA, Output Current=2A, Output Voltage=5V, Switching Frequency=1.1MHz
U201: library part CMP-020-00000-10, "MCU 32-bit STM32 ARM Cortex M4 RISC 512KB Flash 1.8V/2.5V/3.3V 64-Pin LQFP Tray", Case/Package=LQFP, Clock Frequency=84MHz, Max Operating Temperature=85°C, Max Power Dissipation=313mW, Max Supply Voltage=3.6V, Min Operating Temperature=-40°C, Min Supply Voltage=1.7V, Nominal Supply Current=1.8uA, Operating Supply Voltage=3.3V, Package Quantity=960
U301 U302 U303: library part CMP-024-00000-6, "600 V half-bridge gate driver IC with shoot through protection, SOIC 8N, RoHS", Case/Package=SOIC, Max Operating Temperature=150°C, Max Output current=360mA, Max Supply Voltage=20V, Min Operating Temperature=-40°C
U401: library part CMP-016-00000-9, "Precision quad differential comparator, commercial grade 14-TSSOP 0 to 70", Case/Package=TSSOP, Input Bias Current=250nA, Input Offset Voltage (Vos)=3mV, Max Dual Supply Voltage=15V, Max Operating Temperature=70°C, Max Supply Current=500uA, Max Supply Voltage=30V, Min Dual Supply Voltage=1V, Min Operating Temperature=0°C, Min Supply Voltage=2V, Output Current=20mA, Output Current per Channel=6mA, Package Quantity=2000, Quiescent Current=2.5mA, Supply Current=2mA, Voltage Gain=106.02dB
Y201: library part CMP-003-00000-10, "Crystal 24MHz ±10ppm (Tol) ±10ppm (Stability) 12pF FUND 50Ohm 4-Pin Mini-CSMD T/R", Case/Package="4-SMD, No Lead", Frequency=24MHz, Load Capacitance=12pF

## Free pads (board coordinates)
  round 3 hole 3 unplated: MH1(-63.9,29.4) MH2(-63.9,-29.4) MH3(63.9,29.4) MH4(63.9,-29.4)
  round 1.152 hole 1.152 unplated paste-2539.97 mask+0.148: TH(-54,-29.4) TH(-54,29.4) TH(54,-29.4)

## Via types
v1: diameter 0.7, hole 0.3, L1 (Signal) to L4 (Signal), tented top, 308 vias
v2: diameter 0.6, hole 0.2, L1 (Signal) to L4 (Signal), tented top, 78 vias

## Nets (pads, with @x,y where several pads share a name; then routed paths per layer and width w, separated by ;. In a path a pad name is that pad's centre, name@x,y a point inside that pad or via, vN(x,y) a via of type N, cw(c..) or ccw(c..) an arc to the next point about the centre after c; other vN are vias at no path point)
3V3_BUCK_BST: C102.2 U101.6 | length 2.5
  L1 (Signal) w0.5: C102.2@-33.24,14.5 -33.24,12.85 U101.6@-32.4,12.85
3V3_BUCK_EN: R101.1 R102.2 U101.2 | length 3.1
  L1 (Signal) w0.5: R101.1@-36.3,10.5 R102.2@-36.3,11.9 U101.2@-34.6,11.9
3V3_BUCK_SW: C102.1 L101.1 U101.5
3V3_LED_K: D101.1 R103.2 | length 1.9
  L1 (Signal) w0.3: R103.2@-23.75,7 -23.75,7.5 -23.5,7.75 D101.1@-23.5,8.75
4IN+: R404.2 U401.11 | length 2
  L1 (Signal) w0.25: R404.2@-7.4,-14.65 -7.25,-14.5 U401.11@-5.5,-14.5
4IN-: R405.2 U401.10 | length 3.8
  L1 (Signal) w0.25: R405.2@-8.65,-14.65 -8.65,-14.035 -8.465,-13.85 U401.10@-5.5,-13.85
5V_BUCK_BST: C106.2 U102.6 | length 2.5
  L1 (Signal) w0.5: C106.2@-33.24,-7.6 -33.24,-9.25 U102.6@-32.4,-9.25
5V_BUCK_EN: R104.1 R105.2 U102.2 | length 3
  L1 (Signal) w0.5: R104.1@-36.3,-11.5 R105.2@-36.3,-10.2 U102.2@-34.6,-10.2
5V_BUCK_SW: C106.1 L102.1 U102.5
5V_LED_K: D102.1 R106.2 | length 1.9
  L1 (Signal) w0.3: R106.2@-23.75,-15.1 -23.7,-15.05 -23.7,-14.6 -23.5,-14.4 D102.1@-23.5,-13.3
+3V3: C103.2 C104.2 C201.2 C202.2 C203.2 C204.2 C205.2 C206.2 C207.2 C208.2 D101.2 J202.2 L101.2 SW202.3 U101.1 U201.1 U201.13 U201.19 U201.32 U201.48 U201.64 | length 52.6
  L1 (Signal) w0.25: C202.2@-11.7,-2.74 -11.04,-2.74 -10.8,-2.5 U201.13@-9.95,-2.5 U201.13@-9.955,-2.505 ; C203.2@-11.7,3.76 -11.06,3.76 -10.825,3.525 -9.975,3.525 U201.1@-9.95,3.5 ; C205.2@-8.19,7.2 -8.19,6.495 -7.975,6.28 -7.975,5.525 U201.64@-7.95,5.5 ; U201.19@-6.95,-6 -6.95,-6.85 -6.71,-7.09 C204.2@-6.71,-7.75 ; U201.32@-0.45,-6 -0.45,-6.85 -0.3,-7 C206.2@-0.3,-7.53 ; U201.48@1.55,3.5 1.575,3.525 2.325,3.525 2.5,3.7 3.01,3.7 C207.2@3.2,3.89
  L1 (Signal) w0.5: U101.1@-34.6,12.85 v1(-34.6,14.4) ; v1(-15.3,-3.7) -15.262,-3.662 -15.262,-3.587 -14.775,-3.1 -13.55,-3.1 C201.2@-13.5,-3.05 -13.5,-3.015 -13.225,-2.74 C202.2@-11.7,-2.74 ; v1(-14.5,3.9) -14.462,3.862 -13.202,3.862 C208.2@-13.1,3.76 C203.2@-11.7,3.76 ; v1(-12.588,10.412) -11.488,10.412 -11.3,10.6 -11.3,11.65 v1(-11.262,11.688) ; v1(-8.2,8.8) -8.19,8.8 C205.2@-8.19,7.2 ; v1(-8.1,-9.1) -8.062,-9.062 -7.362,-9.062 -6.78,-8.48 -6.78,-7.82 C204.2@-6.71,-7.75 ; C206.2@-0.11,-7.7 -0.11,-8.736 0.1,-8.946 v1(0.1,-9) ; C207.2@3.2,3.89 v1(3.2,5.3)
  L4 (Signal) w0.5: v1(-22.4,14.7) -22.4,20.607 -22.007,21 -14.7,21 -9,26.7 J202.2@-9,29
  other v1: -25.15,11.85 -25.15,12.8 -25.15,13.75 -25.15,14.7 -25.15,15.65
+5V: C107.2 C108.2 C401.2 D102.2 J202.1 L102.2 R401.2 R402.2 R403.2 U102.1 U401.3 | length 49
  L1 (Signal) w0.35: U401.3@0.1,-15.15 2,-15.15 C401.2@2,-15.31
  L1 (Signal) w0.5: v1(-34.671,-7.629) -34.671,-7.683 -34.6,-7.754 -34.6,-9.15 U102.1@-34.6,-9.25 ; C401.2@2,-15.31 3.656,-15.31 3.846,-15.5 v1(3.9,-15.5)
  L4 (Signal) w0.5: v1(-25,-2.8) -25.038,-2.762 -25.038,-0.738 -22.9,1.4 -22.9,4.7 -20.8,6.8 -20.8,19.007 -20.507,19.3 -14.1,19.3 -6.46,26.94 J202.1@-6.46,29
  other v1: -4.2,-20 -2.7,-20 -1.2,-20 -25.15,-10.25 -25.15,-9.3 -25.15,-8.35 -25.15,-7.4 -25.15,-6.45
+VBAT: D103.1 J101.1 J101.2 J101.3 J101.4 Q101.5 Q101.6 Q101.7 Q101.8
  other v1: -44.8,4.4 -44.8,5.8 -44.8,7.2 -47.6,8.6 -46.2,8.6 -44.8,8.6 -43.4,8.6 -42,8.6 -44.8,10 -44.8,11.4 -44.8,12.8 -47.6,14.2 -46.2,14.2 -44.8,14.2 -43.4,14.2 -42,14.2 -47.6,15.6 -46.2,15.6 -44.8,15.6 -43.4,15.6 -42,15.6
  other v2: -48.9,18.2 -47.9,18.2 -48.9,19 -47.9,19 -48.9,19.8 -47.9,19.8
